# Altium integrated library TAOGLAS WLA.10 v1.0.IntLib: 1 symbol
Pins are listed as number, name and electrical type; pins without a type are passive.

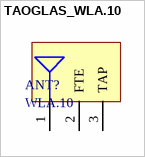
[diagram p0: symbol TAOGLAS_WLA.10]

## TAOGLAS_WLA.10
designator ANT?, comment WLA.10
Dual-Band 2.4GHz/5.8GHz/7.1GHz Wi-Fi Ceramic Substrate Loop Antenna; ComponentLibStatus: Created; MFG: Taoglas; Temp_High: +85C; Temp_Low: -40C
footprint TAOGLAS_WLA.10 (Dual-Band 2.4GHz/5.8GHz/7.1GHz Wi-Fi Ceramic Substrate Loop Antenna)
footprint TAOGLAS_WLA.10_Mirrored (Dual-Band 2.4GHz/5.8GHz/7.1GHz Wi-Fi Ceramic Substrate Loop Antenna)
pins: 1 RF FEED, 2 FTE, 3 TAP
